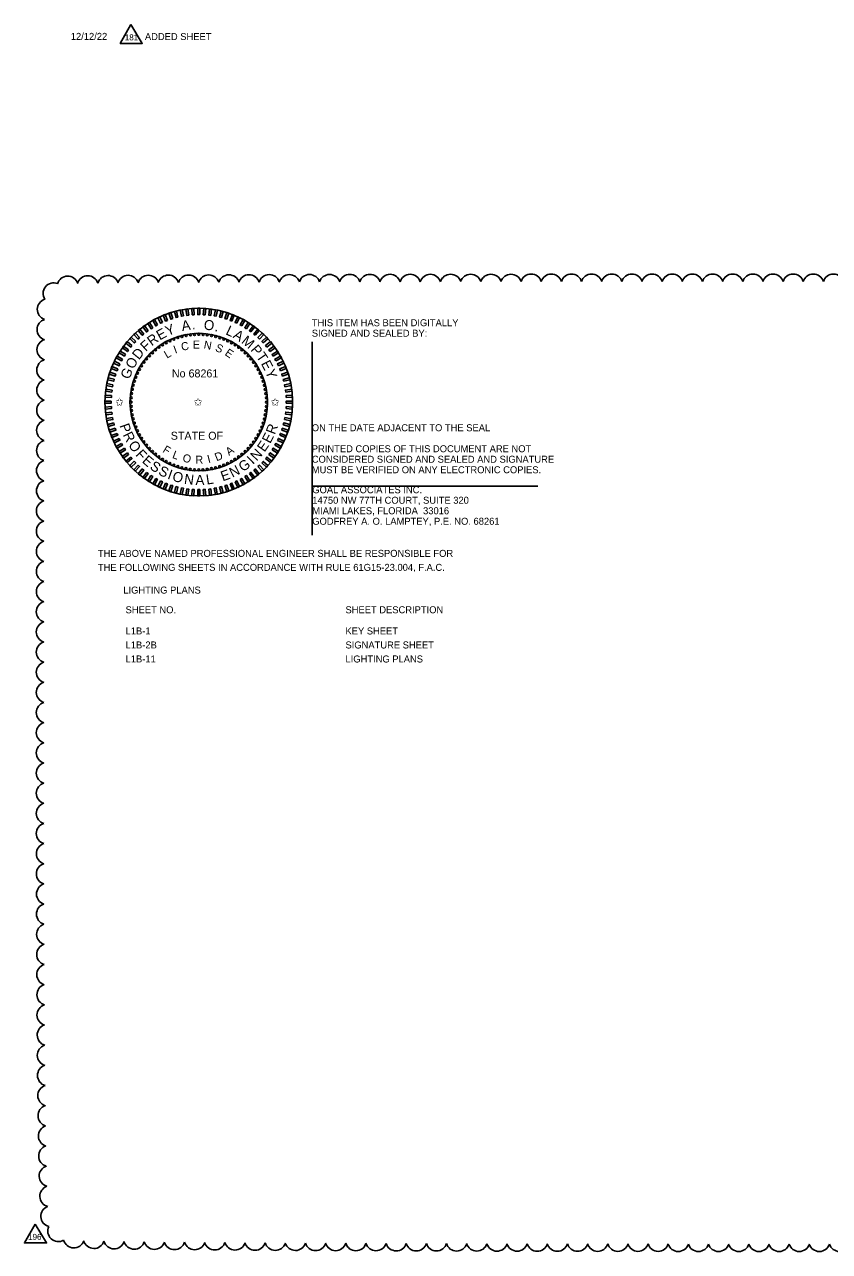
# Model space of a CAD drawing. Extents: x -811.2 to -795, y -2295.2 to -2235.1.
# Drawn here: x -811.23 to -803.18, y -2269.67 to -2257.4 of the extents above; entities that cross this region are included whole.
import ezdxf

# ---------------------------------------------------------------- set-up
doc = ezdxf.new("R2010")
doc.units = 0
for name, color, linetype in [('AdhocPoint_dp', 7, 'Continuous'), ('Cloud_dp', 7, 'Continuous'), ('PlotBorder_dp', 7, 'Continuous'), ('TextMinor', 7, 'Continuous'), ('TextMisc', 7, 'Continuous'), ('TextShtNo', 7, 'Continuous')]:
    doc.layers.add(name, color=color, linetype=linetype)

msp = doc.modelspace()

# ---------------------------------------------------------------- linework, layer by layer
at = {"layer": 'AdhocPoint_dp'}
for p, q in [((-808.355, -2260.573), (-808.355, -2262.508)), ((-808.355, -2262.018), (-806.098, -2262.018))]:
    msp.add_line(p, q, dxfattribs=at)
at = {"layer": 'Cloud_dp'}
for points in [[(-810.168, -2257.402), (-810.276, -2257.59), (-810.055, -2257.59)], [(-811.125, -2269.395), (-811.233, -2269.584), (-811.012, -2269.584)]]:
    msp.add_lwpolyline(points, close=True, dxfattribs=at)
for centre, start, end in [((-810.801, -2260.023), 18.5945, 163.5945), ((-810.6, -2260.019), 18.2142, 163.2142), ((-810.398, -2260.017), 18.047, 163.047), ((-810.197, -2260.015), 17.9467, 162.9467), ((-809.995, -2260.014), 17.8779, 162.8779), ((-809.794, -2260.013), 17.8269, 162.8269), ((-809.592, -2260.012), 17.7872, 162.7872), ((-809.391, -2260.011), 17.7551, 162.7551), ((-809.189, -2260.01), 17.7284, 162.7284), ((-808.988, -2260.009), 17.7058, 162.7058), ((-808.786, -2260.008), 17.6864, 162.6864), ((-808.585, -2260.008), 17.6694, 162.6694), ((-808.383, -2260.007), 17.6544, 162.6544), ((-808.182, -2260.007), 17.6411, 162.6411), ((-807.98, -2260.006), 17.629, 162.629), ((-807.779, -2260.006), 17.6182, 162.6182), ((-807.577, -2260.005), 17.6083, 162.6083), ((-807.376, -2260.005), 17.5992, 162.5992), ((-807.174, -2260.005), 17.5908, 162.5908), ((-806.972, -2260.004), 17.5831, 162.5831), ((-806.771, -2260.004), 17.576, 162.576), ((-806.569, -2260.004), 17.5693, 162.5693), ((-806.368, -2260.004), 17.563, 162.563), ((-806.166, -2260.003), 17.5572, 162.5572), ((-805.965, -2260.003), 17.5517, 162.5517), ((-805.763, -2260.003), 17.5465, 162.5465), ((-805.562, -2260.003), 17.5417, 162.5417), ((-805.36, -2260.003), 17.537, 162.537), ((-805.159, -2260.003), 17.5327, 162.5327), ((-804.957, -2260.002), 17.5285, 162.5285), ((-804.755, -2260.002), 17.5246, 162.5246), ((-804.554, -2260.002), 17.5208, 162.5208), ((-804.352, -2260.002), 17.5172, 162.5172), ((-804.151, -2260.002), 17.5137, 162.5137), ((-803.949, -2260.002), 17.5105, 162.5105), ((-803.748, -2260.002), 17.5073, 162.5073), ((-803.546, -2260.002), 17.5043, 162.5043), ((-803.345, -2260.002), 17.5014, 162.5014), ((-803.143, -2260.002), 17.5, 162.5), ((-810.941, -2260.091), 68.4395, 213.4395), ((-810.999, -2260.25), 106.8045, 251.8045), ((-811.001, -2260.452), 107.0437, 252.0437), ((-811.002, -2260.653), 107.1562, 252.1562), ((-811.004, -2260.855), 107.2253, 252.2253), ((-811.004, -2261.056), 107.2734, 252.2734), ((-811.005, -2261.258), 107.3093, 252.3093), ((-811.006, -2261.459), 107.3374, 252.3374), ((-811.006, -2261.661), 107.3603, 252.3603), ((-811.007, -2261.862), 107.3793, 252.3793), ((-811.007, -2262.064), 107.3954, 252.3954), ((-811.008, -2262.265), 107.4094, 252.4094), ((-811.008, -2262.467), 107.4216, 252.4216), ((-811.008, -2262.669), 107.4323, 252.4323), ((-811.008, -2262.87), 107.442, 252.442), ((-811.008, -2263.072), 107.4506, 252.4506), ((-811.009, -2263.273), 107.4585, 252.4585), ((-811.009, -2263.475), 107.4656, 252.4656), ((-811.009, -2263.676), 107.4722, 252.4722), ((-811.009, -2263.878), 107.4782, 252.4782), ((-811.009, -2264.079), 107.4838, 252.4838), ((-811.009, -2264.281), 107.489, 252.489), ((-811.009, -2264.482), 107.4938, 252.4938), ((-811.009, -2264.684), 107.4984, 252.4984), ((-811.009, -2264.886), 107.5115, 252.5115), ((-811.009, -2265.087), 107.531, 252.531), ((-811.009, -2265.289), 107.5519, 252.5519), ((-811.009, -2265.49), 107.5743, 252.5743), ((-811.008, -2265.692), 107.5985, 252.5985), ((-811.008, -2265.893), 107.6247, 252.6247), ((-811.007, -2266.095), 107.6531, 252.6531), ((-811.007, -2266.296), 107.6841, 252.6841), ((-811.006, -2266.498), 107.7182, 252.7182), ((-811.005, -2266.699), 107.7558, 252.7558), ((-811.004, -2266.901), 107.7976, 252.7976), ((-811.003, -2267.102), 107.8445, 252.8445), ((-811.002, -2267.304), 107.8977, 252.8977), ((-811, -2267.505), 107.9585, 252.9585), ((-810.999, -2267.707), 108.0291, 253.0291), ((-810.997, -2267.908), 108.1124, 253.1124), ((-810.994, -2268.11), 108.2128, 253.2128), ((-810.992, -2268.311), 108.3369, 253.3369), ((-810.988, -2268.513), 108.4961, 253.4961), ((-810.985, -2268.714), 108.7107, 253.7107), ((-810.98, -2268.915), 109.023, 254.023), ((-810.973, -2269.117), 109.542, 254.542), ((-810.964, -2269.317), 110.7101, 255.7101), ((-810.895, -2269.464), 155.0652, 300.0652), ((-810.74, -2269.527), 195.6294, 340.6294), ((-810.539, -2269.533), 196.2647, 341.2647), ((-810.337, -2269.537), 196.5499, 341.5499), ((-810.136, -2269.54), 196.722, 341.722), ((-809.934, -2269.542), 196.8406, 341.8406), ((-809.733, -2269.544), 196.9286, 341.9286), ((-809.531, -2269.546), 196.9974, 341.9974), ((-809.33, -2269.548), 197.053, 342.053), ((-809.128, -2269.549), 197.0992, 342.0992), ((-808.927, -2269.551), 197.1383, 342.1383), ((-808.725, -2269.552), 197.1721, 342.1721), ((-808.524, -2269.553), 197.2016, 342.2016), ((-808.322, -2269.554), 197.2276, 342.2276), ((-808.121, -2269.555), 197.2509, 342.2509), ((-807.919, -2269.556), 197.2717, 342.2717), ((-807.718, -2269.556), 197.2907, 342.2907), ((-807.516, -2269.557), 197.3079, 342.3079), ((-807.315, -2269.558), 197.3237, 342.3237), ((-807.113, -2269.558), 197.3382, 342.3382), ((-806.912, -2269.559), 197.3516, 342.3516), ((-806.71, -2269.559), 197.3641, 342.3641), ((-806.508, -2269.56), 197.3757, 342.3757), ((-806.307, -2269.56), 197.3866, 342.3866), ((-806.105, -2269.561), 197.3967, 342.3967), ((-805.904, -2269.561), 197.4063, 342.4063), ((-805.702, -2269.561), 197.4153, 342.4153), ((-805.501, -2269.562), 197.4238, 342.4238), ((-805.299, -2269.562), 197.4318, 342.4318), ((-805.098, -2269.562), 197.4395, 342.4395), ((-804.896, -2269.562), 197.4467, 342.4467), ((-804.695, -2269.563), 197.4536, 342.4536), ((-804.493, -2269.563), 197.4602, 342.4602), ((-804.292, -2269.563), 197.4664, 342.4664), ((-804.09, -2269.563), 197.4724, 342.4724), ((-803.888, -2269.563), 197.4782, 342.4782), ((-803.687, -2269.563), 197.4837, 342.4837), ((-803.485, -2269.563), 197.4889, 342.4889), ((-803.284, -2269.563), 197.494, 342.494), ((-803.082, -2269.563), 197.4989, 342.4989)]:
    msp.add_arc(centre, 0.106, start, end, dxfattribs=at)
at = {"layer": 'TextMinor'}
for radius in [0.938, 0.688]:
    msp.add_circle((-809.49, -2261.177), radius, dxfattribs=at)
at = {"layer": 'TextShtNo'}
for p, q in [((-809.5, -2262.114), (-809.5, -2262.052)), ((-809.49, -2262.114), (-809.49, -2262.052)), ((-809.48, -2262.114), (-809.48, -2262.052))]:
    msp.add_line(p, q, dxfattribs=at)
for points in [[(-809.853, -2260.381), (-809.872, -2260.389), (-809.898, -2260.333), (-809.88, -2260.324)], [(-809.803, -2260.36), (-809.822, -2260.367), (-809.845, -2260.309), (-809.826, -2260.301)], [(-809.751, -2260.341), (-809.77, -2260.348), (-809.789, -2260.288), (-809.77, -2260.282)], [(-809.698, -2260.327), (-809.717, -2260.332), (-809.733, -2260.271), (-809.713, -2260.266)], [(-809.644, -2260.315), (-809.664, -2260.319), (-809.676, -2260.258), (-809.656, -2260.254)], [(-809.59, -2260.307), (-809.61, -2260.31), (-809.618, -2260.248), (-809.598, -2260.245)], [(-809.535, -2260.303), (-809.555, -2260.304), (-809.559, -2260.242), (-809.539, -2260.241)], [(-809.48, -2260.302), (-809.5, -2260.302), (-809.5, -2260.239), (-809.48, -2260.239)], [(-809.425, -2260.304), (-809.445, -2260.303), (-809.441, -2260.241), (-809.421, -2260.242)], [(-809.37, -2260.31), (-809.39, -2260.307), (-809.383, -2260.246), (-809.363, -2260.248)], [(-809.316, -2260.319), (-809.336, -2260.315), (-809.324, -2260.254), (-809.304, -2260.258)], [(-809.263, -2260.332), (-809.282, -2260.327), (-809.267, -2260.266), (-809.247, -2260.271)], [(-809.21, -2260.348), (-809.229, -2260.342), (-809.21, -2260.282), (-809.191, -2260.288)], [(-809.159, -2260.367), (-809.177, -2260.36), (-809.154, -2260.302), (-809.136, -2260.309)], [(-809.108, -2260.389), (-809.127, -2260.381), (-809.1, -2260.324), (-809.082, -2260.333)], [(-810.04, -2260.496), (-810.056, -2260.509), (-810.095, -2260.461), (-810.08, -2260.448)], [(-809.996, -2260.463), (-810.013, -2260.475), (-810.049, -2260.424), (-810.033, -2260.412)], [(-809.95, -2260.433), (-809.967, -2260.443), (-810.001, -2260.391), (-809.984, -2260.38)], [(-809.903, -2260.405), (-809.92, -2260.415), (-809.951, -2260.36), (-809.933, -2260.35)], [(-809.06, -2260.415), (-809.077, -2260.405), (-809.047, -2260.351), (-809.03, -2260.36)], [(-809.013, -2260.443), (-809.03, -2260.433), (-808.996, -2260.38), (-808.979, -2260.391)], [(-808.968, -2260.475), (-808.984, -2260.463), (-808.947, -2260.413), (-808.931, -2260.424)], [(-808.925, -2260.509), (-808.94, -2260.496), (-808.9, -2260.448), (-808.885, -2260.461)], [(-810.158, -2260.611), (-810.171, -2260.627), (-810.219, -2260.587), (-810.206, -2260.571)], [(-810.121, -2260.57), (-810.135, -2260.585), (-810.18, -2260.542), (-810.167, -2260.528)], [(-810.082, -2260.532), (-810.096, -2260.546), (-810.139, -2260.5), (-810.124, -2260.486)], [(-808.884, -2260.546), (-808.898, -2260.532), (-808.856, -2260.487), (-808.841, -2260.5)], [(-808.845, -2260.585), (-808.859, -2260.571), (-808.814, -2260.528), (-808.8, -2260.543)], [(-808.809, -2260.627), (-808.822, -2260.611), (-808.774, -2260.572), (-808.761, -2260.587)], [(-810.223, -2260.699), (-810.234, -2260.716), (-810.287, -2260.683), (-810.276, -2260.666)], [(-810.192, -2260.654), (-810.204, -2260.671), (-810.254, -2260.634), (-810.243, -2260.618)], [(-808.776, -2260.671), (-808.788, -2260.654), (-808.738, -2260.618), (-808.726, -2260.634)], [(-808.746, -2260.717), (-808.757, -2260.7), (-808.704, -2260.666), (-808.693, -2260.683)], [(-810.3, -2260.845), (-810.307, -2260.864), (-810.365, -2260.841), (-810.358, -2260.822)], [(-810.278, -2260.795), (-810.286, -2260.813), (-810.343, -2260.787), (-810.334, -2260.768)], [(-810.252, -2260.746), (-810.262, -2260.764), (-810.316, -2260.734), (-810.307, -2260.716)], [(-808.718, -2260.764), (-808.728, -2260.747), (-808.673, -2260.716), (-808.664, -2260.734)], [(-808.694, -2260.813), (-808.703, -2260.795), (-808.646, -2260.769), (-808.638, -2260.787)], [(-808.673, -2260.864), (-808.68, -2260.845), (-808.622, -2260.822), (-808.615, -2260.841)], [(-810.335, -2260.949), (-810.34, -2260.969), (-810.401, -2260.953), (-810.396, -2260.934)], [(-810.319, -2260.897), (-810.325, -2260.916), (-810.385, -2260.897), (-810.379, -2260.877)], [(-808.655, -2260.916), (-808.661, -2260.897), (-808.602, -2260.878), (-808.595, -2260.897)], [(-808.64, -2260.969), (-808.645, -2260.95), (-808.585, -2260.934), (-808.58, -2260.954)], [(-810.357, -2261.057), (-810.36, -2261.077), (-810.421, -2261.069), (-810.419, -2261.049)], [(-810.348, -2261.003), (-810.352, -2261.023), (-810.413, -2261.011), (-810.409, -2260.991)], [(-808.629, -2261.023), (-808.632, -2261.003), (-808.571, -2260.991), (-808.567, -2261.011)], [(-808.621, -2261.077), (-808.623, -2261.057), (-808.561, -2261.049), (-808.559, -2261.069)], [(-810.365, -2261.167), (-810.365, -2261.187), (-810.428, -2261.187), (-810.428, -2261.167)], [(-810.363, -2261.112), (-810.364, -2261.132), (-810.426, -2261.128), (-810.425, -2261.108)], [(-808.616, -2261.132), (-808.617, -2261.112), (-808.555, -2261.108), (-808.554, -2261.128)], [(-808.615, -2261.187), (-808.615, -2261.167), (-808.553, -2261.167), (-808.553, -2261.187)], [(-810.364, -2261.222), (-810.363, -2261.242), (-810.425, -2261.246), (-810.426, -2261.226)], [(-810.36, -2261.276), (-810.357, -2261.296), (-810.419, -2261.304), (-810.421, -2261.284)], [(-808.623, -2261.297), (-808.621, -2261.277), (-808.559, -2261.284), (-808.561, -2261.304)], [(-808.617, -2261.242), (-808.616, -2261.222), (-808.554, -2261.226), (-808.555, -2261.246)], [(-810.352, -2261.331), (-810.348, -2261.351), (-810.409, -2261.362), (-810.413, -2261.342)], [(-810.34, -2261.385), (-810.335, -2261.404), (-810.396, -2261.42), (-810.401, -2261.4)], [(-810.325, -2261.438), (-810.319, -2261.457), (-810.379, -2261.476), (-810.385, -2261.457)], [(-808.661, -2261.457), (-808.655, -2261.438), (-808.595, -2261.457), (-808.602, -2261.476)], [(-808.645, -2261.404), (-808.64, -2261.385), (-808.58, -2261.4), (-808.585, -2261.42)], [(-808.632, -2261.351), (-808.629, -2261.331), (-808.567, -2261.343), (-808.571, -2261.363)], [(-810.307, -2261.489), (-810.3, -2261.508), (-810.358, -2261.531), (-810.366, -2261.512)], [(-810.286, -2261.54), (-810.278, -2261.558), (-810.334, -2261.585), (-810.343, -2261.567)], [(-808.703, -2261.559), (-808.694, -2261.54), (-808.638, -2261.567), (-808.646, -2261.585)], [(-808.68, -2261.508), (-808.673, -2261.49), (-808.615, -2261.513), (-808.622, -2261.531)], [(-810.262, -2261.589), (-810.252, -2261.607), (-810.307, -2261.637), (-810.317, -2261.62)], [(-810.234, -2261.637), (-810.224, -2261.654), (-810.276, -2261.688), (-810.287, -2261.671)], [(-810.204, -2261.683), (-810.192, -2261.699), (-810.243, -2261.736), (-810.255, -2261.72)], [(-808.788, -2261.699), (-808.776, -2261.683), (-808.726, -2261.72), (-808.738, -2261.736)], [(-808.757, -2261.654), (-808.746, -2261.637), (-808.693, -2261.671), (-808.704, -2261.688)], [(-808.728, -2261.607), (-808.719, -2261.59), (-808.664, -2261.62), (-808.674, -2261.637)], [(-810.171, -2261.727), (-810.158, -2261.742), (-810.206, -2261.782), (-810.219, -2261.767)], [(-810.135, -2261.768), (-810.121, -2261.783), (-810.167, -2261.826), (-810.18, -2261.811)], [(-810.097, -2261.808), (-810.082, -2261.822), (-810.125, -2261.867), (-810.139, -2261.853)], [(-808.899, -2261.822), (-808.884, -2261.808), (-808.841, -2261.853), (-808.856, -2261.867)], [(-808.859, -2261.783), (-808.845, -2261.769), (-808.8, -2261.811), (-808.814, -2261.826)], [(-808.822, -2261.742), (-808.81, -2261.727), (-808.761, -2261.767), (-808.774, -2261.782)], [(-810.056, -2261.845), (-810.04, -2261.857), (-810.08, -2261.906), (-810.096, -2261.893)], [(-810.013, -2261.879), (-809.996, -2261.891), (-810.033, -2261.941), (-810.049, -2261.929)], [(-809.968, -2261.91), (-809.951, -2261.921), (-809.984, -2261.974), (-810.001, -2261.963)], [(-809.921, -2261.939), (-809.903, -2261.948), (-809.933, -2262.003), (-809.951, -2261.993)], [(-809.077, -2261.949), (-809.06, -2261.939), (-809.03, -2261.994), (-809.047, -2262.003)], [(-809.03, -2261.921), (-809.013, -2261.91), (-808.979, -2261.963), (-808.996, -2261.974)], [(-808.984, -2261.891), (-808.968, -2261.879), (-808.931, -2261.929), (-808.947, -2261.941)], [(-808.94, -2261.858), (-808.925, -2261.845), (-808.885, -2261.893), (-808.9, -2261.906)], [(-809.872, -2261.964), (-809.854, -2261.973), (-809.88, -2262.029), (-809.898, -2262.021)], [(-809.822, -2261.987), (-809.803, -2261.994), (-809.826, -2262.052), (-809.845, -2262.045)], [(-809.77, -2262.006), (-809.751, -2262.012), (-809.77, -2262.072), (-809.789, -2262.065)], [(-809.718, -2262.022), (-809.698, -2262.027), (-809.714, -2262.087), (-809.733, -2262.082)], [(-809.664, -2262.034), (-809.644, -2262.038), (-809.656, -2262.1), (-809.676, -2262.096)], [(-809.61, -2262.044), (-809.59, -2262.046), (-809.598, -2262.108), (-809.618, -2262.106)], [(-809.555, -2262.05), (-809.535, -2262.051), (-809.539, -2262.113), (-809.559, -2262.112)], [(-809.5, -2262.052), (-809.48, -2262.052), (-809.48, -2262.114), (-809.5, -2262.114)], [(-809.445, -2262.051), (-809.425, -2262.05), (-809.421, -2262.112), (-809.441, -2262.113)], [(-809.391, -2262.046), (-809.371, -2262.044), (-809.363, -2262.106), (-809.383, -2262.108)], [(-809.336, -2262.038), (-809.316, -2262.034), (-809.305, -2262.096), (-809.324, -2262.1)], [(-809.282, -2262.027), (-809.263, -2262.022), (-809.247, -2262.082), (-809.267, -2262.087)], [(-809.229, -2262.012), (-809.21, -2262.006), (-809.191, -2262.065), (-809.21, -2262.072)], [(-809.177, -2261.994), (-809.159, -2261.987), (-809.136, -2262.045), (-809.154, -2262.052)], [(-809.127, -2261.973), (-809.108, -2261.964), (-809.082, -2262.021), (-809.1, -2262.029)]]:
    msp.add_lwpolyline(points, close=True, dxfattribs=at)
for centre in [(-809.816, -2260.583), (-809.778, -2260.564), (-809.739, -2260.547), (-809.699, -2260.532), (-809.658, -2260.521), (-809.617, -2260.511), (-809.574, -2260.505), (-809.532, -2260.501), (-809.49, -2260.499), (-809.447, -2260.501), (-809.405, -2260.505), (-809.363, -2260.511), (-809.321, -2260.521), (-809.28, -2260.533), (-809.24, -2260.547), (-809.201, -2260.564), (-809.163, -2260.583), (-809.984, -2260.713), (-809.953, -2260.683), (-809.922, -2260.654), (-809.888, -2260.628), (-809.853, -2260.605), (-809.127, -2260.605), (-809.091, -2260.629), (-809.058, -2260.655), (-809.026, -2260.683), (-808.996, -2260.713), (-810.062, -2260.813), (-810.038, -2260.778), (-810.012, -2260.745), (-808.968, -2260.745), (-808.942, -2260.779), (-808.918, -2260.814), (-810.134, -2260.967), (-810.12, -2260.927), (-810.103, -2260.888), (-810.084, -2260.85), (-808.896, -2260.851), (-808.877, -2260.889), (-808.86, -2260.928), (-808.846, -2260.968), (-810.155, -2261.049), (-810.146, -2261.008), (-808.834, -2261.009), (-808.825, -2261.05), (-810.168, -2261.176), (-810.166, -2261.134), (-810.162, -2261.091), (-808.818, -2261.092), (-808.814, -2261.135), (-808.813, -2261.177), (-810.166, -2261.219), (-810.162, -2261.261), (-810.156, -2261.303), (-808.825, -2261.304), (-808.818, -2261.262), (-808.814, -2261.22), (-810.146, -2261.345), (-810.135, -2261.386), (-810.12, -2261.426), (-808.86, -2261.427), (-808.846, -2261.387), (-808.834, -2261.346), (-810.103, -2261.465), (-810.084, -2261.503), (-810.062, -2261.539), (-810.039, -2261.575), (-808.942, -2261.576), (-808.918, -2261.54), (-808.897, -2261.504), (-808.877, -2261.466), (-810.012, -2261.608), (-809.984, -2261.64), (-809.954, -2261.67), (-809.922, -2261.698), (-809.059, -2261.699), (-809.027, -2261.671), (-808.997, -2261.641), (-808.968, -2261.609), (-809.889, -2261.725), (-809.854, -2261.749), (-809.817, -2261.77), (-809.779, -2261.79), (-809.74, -2261.807), (-809.7, -2261.821), (-809.281, -2261.821), (-809.241, -2261.807), (-809.202, -2261.79), (-809.164, -2261.771), (-809.128, -2261.749), (-809.092, -2261.725), (-809.659, -2261.833), (-809.618, -2261.842), (-809.576, -2261.849), (-809.533, -2261.853), (-809.49, -2261.854), (-809.448, -2261.853), (-809.406, -2261.849), (-809.364, -2261.842), (-809.322, -2261.833)]:
    msp.add_circle(centre, 0.01, dxfattribs=at)

# ---------------------------------------------------------------- texts
at = {"layer": 'Cloud_dp'}
for s, p in [('181', (-810.23, -2257.56)), ('196', (-811.197, -2269.553))]:
    msp.add_text(s, height=0.06, rotation=0, dxfattribs=at).set_placement(p)
at = {"layer": 'PlotBorder_dp'}
for s, p in [('THIS ITEM HAS BEEN DIGITALLY', (-808.36, -2260.418)), ('SIGNED AND SEALED BY:', (-808.36, -2260.523)), ('ON THE DATE ADJACENT TO THE SEAL', (-808.36, -2261.468)), ('PRINTED COPIES OF THIS DOCUMENT ARE NOT ', (-808.36, -2261.678)), ('CONSIDERED SIGNED AND SEALED AND SIGNATURE ', (-808.36, -2261.783)), ('MUST BE VERIFIED ON ANY ELECTRONIC COPIES.', (-808.36, -2261.888)), ('GOAL ASSOCIATES INC.', (-808.355, -2262.088)), ('14750 NW 77TH COURT, SUITE 320', (-808.355, -2262.193)), ('MIAMI LAKES, FLORIDA  33016', (-808.355, -2262.298)), ('GODFREY A. O. LAMPTEY, P.E. NO. 68261', (-808.355, -2262.403)), ('THE ABOVE NAMED PROFESSIONAL ENGINEER SHALL BE RESPONSIBLE FOR ', (-810.499, -2262.724)), ('THE FOLLOWING SHEETS IN ACCORDANCE WITH RULE 61G15-23.004, F.A.C.', (-810.499, -2262.864)), ('LIGHTING PLANS', (-810.245, -2263.091))]:
    msp.add_text(s, height=0.07, dxfattribs=at).set_placement(p)
at = {"layer": 'TextMinor'}
for s, p in [('12/12/22', (-810.77, -2257.555)), ('ADDED SHEET', (-810.029, -2257.557))]:
    msp.add_text(s, height=0.07, dxfattribs=at).set_placement(p)
at = {"layer": 'TextMisc'}
for s, p in [('SHEET NO.', (-810.222, -2263.288)), ('SHEET DESCRIPTION', (-808.023, -2263.288)), ('L1B-1', (-810.222, -2263.5)), ('KEY SHEET', (-808.023, -2263.5)), ('L1B-2B', (-810.222, -2263.64)), ('SIGNATURE SHEET', (-808.023, -2263.64)), ('L1B-11', (-810.222, -2263.78)), ('LIGHTING PLANS', (-808.023, -2263.78))]:
    msp.add_text(s, height=0.07, dxfattribs=at).set_placement(p)
at = {"layer": 'TextShtNo'}
for s, height, rotation, p in [('E', 0.1, 28.1055, (-809.881, -2260.561)), ('Y', 0.1, 21.0633, (-809.802, -2260.517)), ('A', 0.1, 8.8088, (-809.655, -2260.466)), ('.', 0.1, 1.0418, (-809.558, -2260.45)), ('O', 0.1, 352.1877, (-809.445, -2260.449)), ('.', 0.1, 343.5268, (-809.336, -2260.464)), ('L', 0.1, 334.6727, (-809.228, -2260.496)), ('A', 0.1, 328.4096, (-809.155, -2260.529)), ('F', 0.1, 42.3772, (-810.02, -2260.676)), ('R', 0.1, 35.9269, (-809.961, -2260.62)), ('C', 0.08, 12.2025, (-809.658, -2260.665)), ('E', 0.08, 0.4186, (-809.55, -2260.642)), ('N', 0.08, 349.2914, (-809.445, -2260.64)), ('M', 0.1, 320.6426, (-809.071, -2260.58)), ('D', 0.1, 50.8569, (-810.089, -2260.76)), ('L', 0.08, 30.4021, (-809.809, -2260.743)), ('I', 0.08, 20.0117, (-809.726, -2260.693)), ('S', 0.08, 337.0221, (-809.332, -2260.662)), ('E', 0.08, 325.8663, (-809.236, -2260.702)), ('P', 0.1, 311.1966, (-808.978, -2260.657)), ('T', 0.1, 304.4563, (-808.921, -2260.721)), ('O', 0.1, 59.5178, (-810.145, -2260.854)), ('E', 0.1, 297.6315, (-808.871, -2260.791)), ('G', 0.1, 68.0518, (-810.185, -2260.955)), ('Y', 0.1, 290.5893, (-808.828, -2260.87)), ('P', 0.1, 289.4055, (-810.285, -2261.411)), ('R', 0.1, 69.5134, (-808.73, -2261.507)), ('R', 0.1, 296.1458, (-810.252, -2261.503)), ('O', 0.1, 303.9671, (-810.2, -2261.604)), ('E', 0.1, 55.4289, (-808.833, -2261.682)), ('E', 0.1, 62.4712, (-808.776, -2261.597)), ('F', 0.1, 312.628, (-810.128, -2261.706)), ('F', 0.08, 328.7241, (-809.858, -2261.673)), ('L', 0.08, 339.2916, (-809.761, -2261.733)), ('D', 0.08, 22.0128, (-809.312, -2261.769)), ('A', 0.08, 34.4992, (-809.188, -2261.716)), ('N', 0.1, 47.1788, (-808.912, -2261.771)), ('E', 0.1, 319.0783, (-810.064, -2261.774)), ('S', 0.1, 326.1206, (-809.987, -2261.84)), ('O', 0.08, 349.6821, (-809.656, -2261.772)), ('R', 0.08, 2.3398, (-809.522, -2261.794)), ('I', 0.08, 14.2037, (-809.394, -2261.787)), ('N', 0.1, 26.8614, (-809.154, -2261.934)), ('G', 0.1, 35.1115, (-809.049, -2261.878)), ('I', 0.1, 43.6456, (-808.95, -2261.805)), ('S', 0.1, 333.193, (-809.902, -2261.896)), ('I', 0.1, 340.2654, (-809.81, -2261.941)), ('O', 0.1, 343.7986, (-809.762, -2261.96)), ('N', 0.1, 352.4595, (-809.641, -2261.992)), ('A', 0.1, 0.7097, (-809.523, -2262.005)), ('L', 0.1, 8.4767, (-809.41, -2262.002)), ('E', 0.1, 19.8191, (-809.25, -2261.97))]:
    msp.add_text(s, height=height, rotation=rotation, dxfattribs=at).set_placement(p)
for s, p in [('No 68261', (-809.759, -2260.93)), ('✩', (-810.325, -2261.215)), ('✩', (-809.54, -2261.215)), ('✩', (-808.769, -2261.215)), ('STATE OF', (-809.77, -2261.553))]:
    msp.add_text(s, height=0.08, dxfattribs=at).set_placement(p)

doc.saveas('drawing.dxf')
